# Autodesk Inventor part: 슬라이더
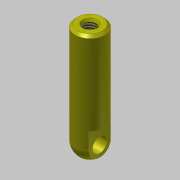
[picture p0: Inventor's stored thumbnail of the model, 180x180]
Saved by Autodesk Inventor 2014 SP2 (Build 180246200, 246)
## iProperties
Created: 2016-08
Part Number: 슬라이더
Material: 강철, 탄소
Document SubType Name: Modeling
Designer: mduedu
Density: 7.87 g/cm^3
Appearance: 노란색
Author: mduedu
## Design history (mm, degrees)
sketch "스케치1"
  geometry: C1 r 6 at (0, 0); 1 further point
  constraints: 1 centre point, 1 coincident
  dimensions: "d0" = 12 diameter of C1
extrude "돌출1" new body sketch "스케치1" distance "d1" = 47; taper "d2" = 0 deg
fillet "모깎기1" dims "d21" = 6
sketch "스케치6"
  geometry: L1 (6, 6)-(6, 47) reference; L2 (-6, 6)-(-6, 47) reference; L3 (6, 47)-(-6, 47) reference; L4 (0, 47)-(0, 0); L5 (6, 13)-(4, 13); L6 (4, 13)-(4, 0); L7 (4, 0)-(6, 0); L8 (6, 0)-(6, 13); L9 (-6, 13)-(-4, 13); L10 (-4, 13)-(-4, 0); L11 (-4, 0)-(-6, 0); L12 (-6, 0)-(-6, 13)
  constraints: 18 end point, 4 symmetric about line, 2 parallel, 2 perpendicular, 1 horizontal, 1 horizontal alignment, 1 midpoint, 1 point on line
  dimensions: "d22" = 13 distance of L7.end L5.start; "d24" = 4 distance between parallel lines of L6 L4
extrude "돌출5" cut sketch "스케치6" stored distance "d25" = 8; taper "d26" = 0 deg
sketch "스케치8"
  geometry: C1 r 3 at (6, 0); 1 further point
  constraints: 1 centre point, 1 horizontal alignment
  dimensions: "d27" = 6 diameter of C1; "d28" = 6 distance of point (0, 0) C1.centre
extrude "돌출6" cut sketch "스케치8" stored distance "d29" = 8; taper "d30" = 0 deg
hole "구멍1" diameter "d33" = 4.917; stored, may be unused: countersink angle "d37" = 90 deg, drill point angle "d39" = 118 deg; dims "d31" = 10, "d32" = 10, "d34" = 10, "d35" = 4, "d36" = 2, "d38" = 12
chamfer "모따기1" distance "d40" = 1; stored, may be unused: second distance "d41" = 2, angle "d42" = 30 deg
chamfer "모따기2" distance "d43" = 1; stored, may be unused: second distance "d44" = 2, angle "d45" = 30 deg
node "솔리드1"
